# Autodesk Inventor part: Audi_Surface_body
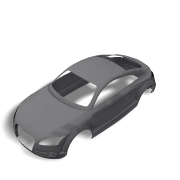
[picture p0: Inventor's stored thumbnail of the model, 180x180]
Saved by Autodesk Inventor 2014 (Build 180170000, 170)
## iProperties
Created: 2015-04
Part Number: Audi_Surface_body
Material: Generic
Document SubType Name: Modeling
Designer: Aluno
Density: 1 g/cm^3
Appearance: 153,153,153
Author: nauman
Title: C:\Users\nauman\Desktop\Audi_Surface_body.IGS
Creation Date: 2012-06-07
Sending System: SolidWorks 2012
Preprocessor: SolidWorks 2012
Minimum Resolution: 0.0
Sending System Product ID: Audi_Surface_body
Receiving System Product ID: Audi_Surface_body
Sent Units: Millimeter
Translation Standard: IGES 5.3
Model Creation Time: 2012-06-07
Author: Aluno
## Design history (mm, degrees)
node "Audi_Surface_body1"
thicken "Thicken1" dims "d0" = 1, "d1" = 1
thicken "Thicken2" dims "d2" = 1, "d3" = 1
thicken "Thicken3" dims "d4" = 1, "d5" = 1
thicken "Thicken4" dims "d6" = 1, "d7" = 1
thicken "Thicken5" dims "d8" = 1, "d9" = 1
thicken "Thicken6" dims "d10" = 1, "d11" = 1
thicken "Thicken7" dims "d12" = 1, "d13" = 1
thicken "Thicken8" dims "d14" = 1, "d15" = 1
thicken "Thicken9" dims "d16" = 1, "d17" = 1
thicken "Thicken10" dims "d18" = 1, "d19" = 1
thicken "Thicken11" dims "d20" = 1, "d21" = 1
thicken "Thicken12" dims "d22" = 1, "d23" = 1
thicken "Thicken13" dims "d24" = 1, "d25" = 1
thicken "Thicken14" dims "d26" = 1, "d27" = 1
thicken "Thicken15" dims "d28" = 1, "d29" = 1
thicken "Thicken16" dims "d30" = 1, "d31" = 1
thicken "Thicken17" dims "d32" = 1, "d33" = 1
thicken "Thicken18" dims "d34" = 1, "d35" = 1
thicken "Thicken19" dims "d36" = 1, "d37" = 1
thicken "Thicken20" dims "d38" = 1, "d39" = 1
thicken "Thicken21" dims "d40" = 1, "d41" = 1
thicken "Thicken22" dims "d42" = 1, "d43" = 1
thicken "Thicken23" dims "d44" = 1, "d45" = 1
thicken "Thicken24" dims "d46" = 1, "d47" = 1
thicken "Thicken25" dims "d48" = 1, "d49" = 1
thicken "Thicken26" dims "d50" = 1, "d51" = 1
thicken "Thicken27" dims "d52" = 1, "d53" = 1
thicken "Thicken28" dims "d54" = 1, "d55" = 1
thicken "Thicken29" dims "d56" = 1, "d57" = 1
thicken "Thicken30" dims "d58" = 1, "d59" = 1
thicken "Thicken31" dims "d60" = 1, "d61" = 1
thicken "Thicken32" dims "d62" = 1, "d63" = 1
thicken "Thicken33" dims "d64" = 1, "d65" = 1
thicken "Thicken34" dims "d66" = 1, "d67" = 1
thicken "Thicken35" dims "d68" = 1, "d69" = 1
thicken "Thicken36" dims "d70" = 1, "d71" = 1
thicken "Thicken37" dims "d72" = 1, "d73" = 1
thicken "Thicken38" dims "d74" = 1, "d75" = 1
thicken "Thicken39" dims "d76" = 1, "d77" = 1
thicken "Thicken40" dims "d78" = 1, "d79" = 1
thicken "Thicken41" dims "d80" = 1, "d81" = 1
thicken "Thicken42" dims "d82" = 1, "d83" = 1
thicken "Thicken43" dims "d84" = 1, "d85" = 1
thicken "Thicken44" dims "d86" = 1, "d87" = 1
thicken "Thicken45" dims "d88" = 1, "d89" = 1
thicken "Thicken46" dims "d90" = 1, "d91" = 1
thicken "Thicken47" dims "d92" = 1, "d93" = 1
thicken "Thicken48" dims "d94" = 1, "d95" = 1
thicken "Thicken49" dims "d96" = 1, "d97" = 1
thicken "Thicken50" dims "d98" = 1, "d99" = 1
thicken "Thicken51" dims "d100" = 1, "d101" = 1
thicken "Thicken52" dims "d102" = 1, "d103" = 1
thicken "Thicken53" dims "d104" = 1, "d105" = 1
thicken "Thicken54" dims "d106" = 1, "d107" = 1
thicken "Thicken55" dims "d108" = 1, "d109" = 1
thicken "Thicken56" dims "d110" = 1, "d111" = 1
thicken "Thicken57" dims "d112" = 1, "d113" = 1
thicken "Thicken58" dims "d114" = 1, "d115" = 1
thicken "Thicken59" dims "d116" = 1, "d117" = 1
thicken "Thicken60" dims "d118" = 1, "d119" = 1
thicken "Thicken61" dims "d120" = 1, "d121" = 1
thicken "Thicken62" dims "d122" = 1, "d123" = 1
thicken "Thicken63" dims "d124" = 1, "d125" = 1
thicken "Thicken64" dims "d126" = 1, "d127" = 1
thicken "Thicken65" dims "d128" = 1, "d129" = 1
thicken "Thicken66" dims "d130" = 1, "d131" = 1
thicken "Thicken67" dims "d132" = 1, "d133" = 1
thicken "Thicken68" dims "d134" = 1, "d135" = 1
thicken "Thicken69" dims "d136" = 1, "d137" = 1
thicken "Thicken70" dims "d138" = 1, "d139" = 1
thicken "Thicken71" dims "d140" = 1, "d141" = 1
thicken "Thicken72" dims "d142" = 1, "d143" = 1
thicken "Thicken73" dims "d144" = 1, "d145" = 1
thicken "Thicken74" dims "d146" = 1, "d147" = 1
thicken "Thicken75" dims "d148" = 1, "d149" = 1
thicken "Thicken76" dims "d150" = 1, "d151" = 1
thicken "Thicken77" dims "d152" = 1, "d153" = 1
thicken "Thicken78" dims "d154" = 1, "d155" = 1
thicken "Thicken79" dims "d156" = 1, "d157" = 1
thicken "Thicken80" dims "d158" = 1, "d159" = 1
thicken "Thicken81" dims "d160" = 1, "d161" = 1
thicken "Thicken82" dims "d162" = 1, "d163" = 1
thicken "Thicken83" dims "d164" = 1, "d165" = 1
thicken "Thicken84" dims "d166" = 1, "d167" = 1
thicken "Thicken85" dims "d168" = 1, "d169" = 1
thicken "Thicken86" dims "d170" = 1, "d171" = 1
thicken "Thicken87" dims "d172" = 1, "d173" = 1
thicken "Thicken88" dims "d174" = 1, "d175" = 1
thicken "Thicken89" dims "d176" = 1, "d177" = 1
thicken "Thicken90" dims "d178" = 1, "d179" = 1
thicken "Thicken91" dims "d180" = 1, "d181" = 1
thicken "Thicken92" dims "d182" = 1, "d183" = 1
thicken "Thicken93" dims "d184" = 1, "d185" = 1
thicken "Thicken94" dims "d186" = 1, "d187" = 1
thicken "Thicken95" dims "d188" = 1, "d189" = 1
thicken "Thicken96" dims "d190" = 1, "d191" = 1
thicken "Thicken97" dims "d192" = 1, "d193" = 1
thicken "Thicken98" dims "d194" = 1, "d195" = 1
thicken "Thicken99" dims "d196" = 1, "d197" = 1
thicken "Thicken100" dims "d198" = 1, "d199" = 1
thicken "Thicken101" dims "d200" = 1, "d201" = 1
thicken "Thicken102" dims "d202" = 1, "d203" = 1
thicken "Thicken103" dims "d204" = 1, "d205" = 1
thicken "Thicken104" dims "d206" = 1, "d207" = 1
thicken "Thicken105" dims "d208" = 1, "d209" = 1
thicken "Thicken106" dims "d210" = 1, "d211" = 1
thicken "Thicken107" dims "d212" = 1, "d213" = 1
thicken "Thicken108" dims "d214" = 1, "d215" = 1
thicken "Thicken109" dims "d216" = 1, "d217" = 1
thicken "Thicken110" dims "d218" = 1, "d219" = 1
thicken "Thicken111" dims "d220" = 1, "d221" = 1
thicken "Thicken112" dims "d222" = 1, "d223" = 1
thicken "Thicken113" dims "d224" = 1, "d225" = 1
thicken "Thicken114" dims "d226" = 1, "d227" = 1
thicken "Thicken115" dims "d228" = 1, "d229" = 1
thicken "Thicken116" dims "d230" = 1, "d231" = 1
thicken "Thicken117" dims "d232" = 1, "d233" = 1
thicken "Thicken118" dims "d234" = 1, "d235" = 1
thicken "Thicken119" dims "d236" = 1, "d237" = 1
thicken "Thicken120" dims "d238" = 1, "d239" = 1
thicken "Thicken121" dims "d240" = 1, "d241" = 1
thicken "Thicken122" dims "d242" = 1, "d243" = 1
thicken "Thicken123" dims "d244" = 1, "d245" = 1
thicken "Thicken124" dims "d246" = 1, "d247" = 1
thicken "Thicken125" dims "d248" = 1, "d249" = 1
thicken "Thicken126" dims "d250" = 1, "d251" = 1
thicken "Thicken127" dims "d252" = 1, "d253" = 1
thicken "Thicken128" dims "d254" = 1, "d255" = 1
thicken "Thicken129" dims "d256" = 1, "d257" = 1
thicken "Thicken130" dims "d258" = 1, "d259" = 1
thicken "Thicken131" dims "d260" = 1, "d261" = 1
thicken "Thicken132" dims "d262" = 1, "d263" = 1
thicken "Thicken133" dims "d264" = 1, "d265" = 1
thicken "Thicken134" dims "d266" = 1, "d267" = 1
thicken "Thicken135" dims "d268" = 1, "d269" = 1
thicken "Thicken136" dims "d270" = 1, "d271" = 1
thicken "Thicken137" dims "d272" = 1, "d273" = 1
thicken "Thicken138" dims "d274" = 1, "d275" = 1
thicken "Thicken139" dims "d276" = 1, "d277" = 1
thicken "Thicken140" dims "d278" = 0.5, "d279" = 0.5
body "Solid1"
body "Solid2"
body "Solid3"
body "Solid4"
body "Solid5"
body "Solid6"
body "Solid7"
body "Solid8"
body "Solid9"
body "Solid10"
body "Solid11"
body "Solid12"
body "Solid13"
body "Solid14"
body "Solid15"
body "Solid16"
body "Solid17"
body "Solid18"
body "Solid19"
body "Solid20"
body "Solid21"
body "Solid22"
body "Solid23"
body "Solid24"
body "Solid25"
body "Solid26"
body "Solid27"
body "Solid28"
body "Solid29"
body "Solid30"
body "Solid31"
body "Solid32"
body "Solid33"
body "Solid34"
body "Solid35"
body "Solid36"
body "Solid37"
body "Solid38"
body "Solid39"
body "Solid40"
body "Solid41"
body "Solid42"
body "Solid43"
body "Solid44"
body "Solid45"
body "Solid46"
body "Solid47"
body "Solid48"
body "Solid49"
body "Solid50"
body "Solid51"
body "Solid52"
body "Solid53"
body "Solid54"
body "Solid55"
body "Solid56"
body "Solid57"
body "Solid58"
body "Solid59"
body "Solid60"
body "Solid61"
body "Solid62"
body "Solid63"
body "Solid64"
body "Solid65"
body "Solid66"
body "Solid67"
body "Solid68"
body "Solid69"
body "Solid70"
body "Solid71"
body "Solid72"
body "Solid73"
body "Solid74"
body "Solid75"
body "Solid76"
body "Solid77"
body "Solid78"
body "Solid79"
body "Solid80"
body "Solid81"
body "Solid82"
body "Solid83"
body "Solid84"
body "Solid85"
body "Solid86"
body "Solid87"
body "Solid88"
body "Solid89"
body "Solid90"
body "Solid91"
body "Solid92"
body "Solid93"
body "Solid94"
body "Solid95"
body "Solid96"
body "Solid97"
body "Solid98"
body "Solid99"
body "Solid100"
body "Solid101"
body "Solid102"
body "Solid103"
body "Solid104"
body "Solid105"
body "Solid106"
body "Solid107"
body "Solid108"
body "Solid109"
body "Solid110"
body "Solid111"
body "Solid112"
body "Solid113"
body "Solid114"
body "Solid115"
body "Solid116"
body "Solid117"
body "Solid118"
body "Solid119"
body "Solid120"
body "Solid121"
body "Solid122"
body "Solid123"
body "Solid124"
body "Solid125"
body "Solid126"
body "Solid127"
body "Solid128"
body "Solid129"
body "Solid130"
body "Solid131"
feature "Composite1"
body "Srf1"
